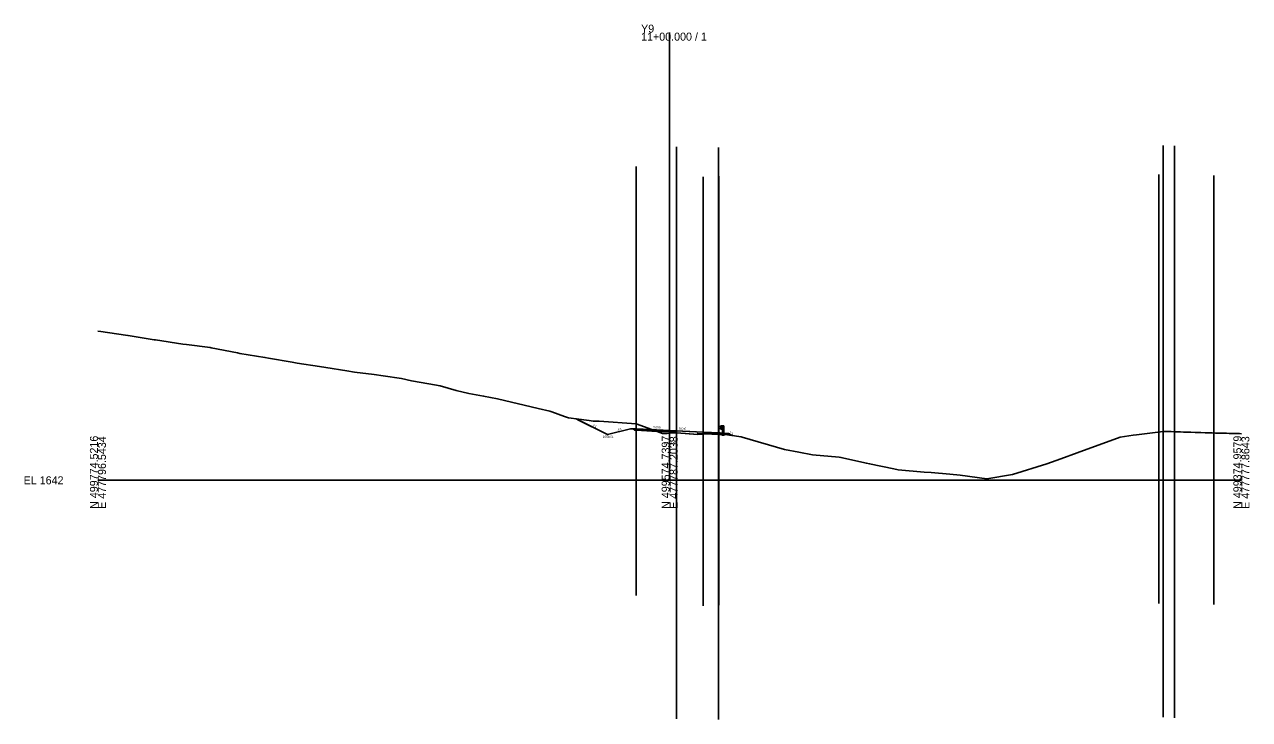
# Model space of a CAD drawing. Extents: x -26 to 403, y -99 to 4540.
# Drawn here: x -25.7 to 402.8, y 916.4 to 1159.4 of the extents above; entities that cross this region are included whole.
import ezdxf

# ---------------------------------------------------------------- set-up
doc = ezdxf.new("R2010")
doc.units = 0
for name, color, linetype in [('Exist Cross Section Cell', 7, 'Continuous'), ('Exist XS Center Line Elevation Label', 7, 'Continuous'), ('Exist XS Ground Line', 7, 'Continuous'), ('Prop XS Ditch Slope Text', 7, 'Continuous'), ('Prop XS Ditch Standard Text', 7, 'Continuous'), ('Prop XS Dump Level', 7, 'Continuous'), ('Prop XS Earthwork Shape', 7, 'Continuous'), ('Prop XS EOT Tick Mark', 7, 'Continuous'), ('Prop XS Finish Grade', 7, 'Continuous'), ('Prop XS Finish Grade Earthwork', 7, 'Continuous'), ('Prop XS Finish Grade Paved Shoulder', 7, 'Continuous'), ('Prop XS Finish Grade Pavement', 7, 'Continuous'), ('Prop XS Guardrail', 7, 'Continuous'), ('Prop XS Hydro Typical Ditch Data', 7, 'Continuous'), ('Prop XS Pvmt Edge Slope', 7, 'Continuous'), ('Prop XS SE Text', 7, 'Continuous'), ('Prop XS Shoulder Borrow Shape', 7, 'Continuous'), ('Prop XS Side Slope Text', 7, 'Continuous'), ('Prop XS Subgrade Earthwork', 7, 'Continuous'), ('Scratch_Level_1', 7, 'Continuous'), ('Scratch_Level_2', 7, 'Continuous'), ('Scratch_Level_5', 7, 'Continuous'), ('Scratch_Level_6', 7, 'Continuous')]:
    doc.layers.add(name, color=color, linetype=linetype)

msp = doc.modelspace()

# ---------------------------------------------------------------- linework, layer by layer
at = {"layer": 'Exist Cross Section Cell'}
for p, q in [((200, 1000), (200, 1156.54)), ((0, 1000), (200, 1000)), ((200, 1000), (400, 1000))]:
    msp.add_line(p, q, dxfattribs=at)
at = {"layer": 'Exist XS Ground Line'}
msp.add_lwpolyline([(0, 1052.18), (0.99, 1052.04), (9.6, 1050.76), (10.56, 1050.58), (19.62, 1049.15), (20.13, 1049.09), (29.69, 1047.62), (31.03, 1047.45), (39.26, 1046.4), (39.64, 1046.34), (48.82, 1044.55), (49.65, 1044.39), (58.39, 1042.98), (59.67, 1042.73), (67.95, 1041.28), (69.68, 1041), (77.52, 1039.74), (79.69, 1039.41), (87.09, 1038.28), (89.71, 1037.84), (96.65, 1036.96), (99.72, 1036.52), (106.22, 1035.55), (109.73, 1034.84), (115.78, 1033.71), (119.74, 1033.01), (125.35, 1031.36), (129.76, 1030.39), (134.91, 1029.48), (139.77, 1028.52), (153.97, 1025.14), (158.05, 1024.18), (158.79, 1023.92), (163.22, 1022.34), (164.56, 1021.87), (171.85, 1020.9), (173.26, 1020.73), (175.35, 1020.64), (188.27, 1019.77), (193.75, 1017.82), (197.47, 1016.41), (199.18, 1016.39), (200, 1016.45), (202.39, 1016.62), (205.54, 1016.38), (209.83, 1016.02), (213.44, 1016.28), (217.04, 1016.36), (224.98, 1015.23), (225.42, 1015.1), (240.14, 1010.83), (245.22, 1009.83), (249.91, 1008.92), (259.27, 1008.1), (259.92, 1008), (268.83, 1005.96), (269.94, 1005.77), (278.4, 1004.04), (279.96, 1003.71), (289, 1002.81), (291.43, 1002.7), (297.96, 1002.18), (301.61, 1001.76), (310.96, 1000.52), (319.97, 1002.04), (331.92, 1005.71), (336.79, 1007.52), (342.54, 1009.56), (357.6, 1015.14), (362.12, 1015.8), (363.27, 1015.94), (365.16, 1016.18), (368.88, 1016.64), (372.6, 1017.12), (374.23, 1017.05), (374.6, 1017.03), (375.39, 1017.01), (376.59, 1016.97), (377.89, 1016.92), (378.66, 1016.9), (379.78, 1016.86), (380.58, 1016.84), (382.3, 1016.78), (383.84, 1016.74), (384.78, 1016.71), (385.82, 1016.68), (387.29, 1016.64), (388.63, 1016.61), (389.79, 1016.57), (391, 1016.54), (392.3, 1016.5), (393.74, 1016.47), (394.81, 1016.44), (395.78, 1016.41), (397.29, 1016.37), (398.49, 1016.34), (399.37, 1016.32), (400, 1016.31)], dxfattribs=at)
at = {"layer": 'Prop XS Dump Level'}
for p, q in [((191, 1017.89), (200, 1017.44)), ((200, 1017.44), (209, 1016.99))]:
    msp.add_line(p, q, dxfattribs=at)
at = {"layer": 'Prop XS Earthwork Shape'}
for points in [[(187.28, 1018.02), (186.3, 1018.01), (178.3, 1016.01), (167.3, 1021.5), (171.85, 1020.9), (173.26, 1020.73), (175.35, 1020.64), (188.27, 1019.77), (193.75, 1017.82), (195.6, 1017.12), (188.3, 1017.48), (187.78, 1017.51)], [(200, 1016.45), (202.39, 1016.62), (202.39, 1016.78), (200, 1016.9), (195.6, 1017.12), (197.47, 1016.41), (199.18, 1016.39)], [(211.7, 1016.31), (209.83, 1016.41), (209.83, 1016.02), (212.98, 1016.25)], [(217.04, 1016.36), (217.96, 1016.23), (217.74, 1016.01), (217.17, 1016.04), (212.98, 1016.25), (213.44, 1016.28)], [(219.17, 1016.42), (221.1, 1015.78), (217.96, 1016.23), (218.23, 1016.5)]]:
    msp.add_lwpolyline(points, close=True, dxfattribs=at)
at = {"layer": 'Prop XS EOT Tick Mark'}
for p, q in [((188.3, 1018.03), (188.3, 1019.03)), ((211.7, 1016.86), (211.7, 1017.86))]:
    msp.add_line(p, q, dxfattribs=at)
at = {"layer": 'Prop XS Finish Grade'}
for p, q in [((188.3, 1018.03), (187.28, 1018.02)), ((217.61, 1016.56), (218.66, 1016.48))]:
    msp.add_line(p, q, dxfattribs=at)
at = {"layer": 'Prop XS Finish Grade Earthwork'}
for p, q in [((178.3, 1016.01), (167.3, 1021.5)), ((186.3, 1018.01), (178.3, 1016.01)), ((187.28, 1018.02), (186.3, 1018.01)), ((218.66, 1016.48), (220.61, 1016.32)), ((220.6, 1016.32), (221.91, 1015.67))]:
    msp.add_line(p, q, dxfattribs=at)
at = {"layer": 'Prop XS Finish Grade Paved Shoulder'}
msp.add_line((211.7, 1016.86), (217.61, 1016.56), dxfattribs=at)
at = {"layer": 'Prop XS Finish Grade Pavement'}
for p, q in [((188.3, 1018.03), (200, 1017.44)), ((200, 1017.44), (211.7, 1016.86))]:
    msp.add_line(p, q, dxfattribs=at)
at = {"layer": 'Prop XS Guardrail'}
for p, q in [((217.93, 1019.04), (217.64, 1018.84)), ((217.93, 1018.51), (217.64, 1018.71)), ((217.93, 1018.41), (217.64, 1018.21)), ((217.93, 1017.88), (217.64, 1018.08)), ((218.43, 1019.04), (217.93, 1019.04)), ((217.93, 1019.04), (217.93, 1017.88)), ((217.93, 1018.46), (217.93, 1018.51)), ((217.93, 1018.46), (217.93, 1018.41)), ((218.43, 1017.88), (217.93, 1017.88)), ((218.43, 1019.04), (218.43, 1016.55)), ((218.43, 1019.04), (218.92, 1019.04)), ((218.43, 1016.55), (218.92, 1016.55)), ((218.43, 1016.55), (218.43, 1015.54)), ((218.92, 1019.04), (218.92, 1016.55)), ((218.92, 1016.55), (218.92, 1015.54))]:
    msp.add_line(p, q, dxfattribs=at)
for centre, start, end in [((217.68, 1018.77), 125.003, 235.0112), ((217.68, 1018.15), 125.0059, 235.0366)]:
    msp.add_arc(centre, 0.0776, start, end, dxfattribs=at)
at = {"layer": 'Prop XS Hydro Typical Ditch Data'}
for p, q in [((178.3, 1016.01), (167.91, 1021.2)), ((186.3, 1018.01), (178.3, 1016.01))]:
    msp.add_line(p, q, dxfattribs=at)
at = {"layer": 'Prop XS Pvmt Edge Slope'}
for p, q in [((188.3, 1018.03), (187.78, 1017.51)), ((217.61, 1016.56), (218.18, 1015.99))]:
    msp.add_line(p, q, dxfattribs=at)
at = {"layer": 'Prop XS Shoulder Borrow Shape'}
for points in [[(188.3, 1018.03), (187.28, 1018.02), (187.78, 1017.51)], [(217.17, 1016.58), (218.23, 1016.5), (217.74, 1016.01)]]:
    msp.add_lwpolyline(points, close=True, dxfattribs=at)
at = {"layer": 'Prop XS Subgrade Earthwork'}
for p, q in [((187.78, 1017.51), (187.28, 1018.02)), ((188.3, 1017.48), (187.78, 1017.51)), ((200, 1016.9), (188.3, 1017.48)), ((202.39, 1016.78), (200, 1016.9)), ((202.39, 1016.62), (202.39, 1016.78)), ((211.7, 1016.31), (209.83, 1016.41)), ((209.83, 1016.02), (209.83, 1016.41)), ((211.69, 1016.31), (217.61, 1016.02)), ((217.61, 1016.02), (218.18, 1015.99)), ((218.18, 1015.99), (218.66, 1016.48))]:
    msp.add_line(p, q, dxfattribs=at)
at = {"layer": 'Scratch_Level_1'}
for p, q in [((202.39, 1116.62), (202.39, 916.62)), ((217.04, 1116.36), (217.04, 916.36)), ((372.6, 1117.12), (372.6, 917.12)), ((376.59, 1116.97), (376.59, 916.97))]:
    msp.add_line(p, q, dxfattribs=at)
at = {"layer": 'Scratch_Level_2'}
for p, q in [((217.17, 1066.34), (217.17, 966.34)), ((371.12, 1066.93), (371.12, 966.93))]:
    msp.add_line(p, q, dxfattribs=at)
at = {"layer": 'Scratch_Level_5'}
for p, q in [((217.17, 1106.34), (217.17, 956.34)), ((371.12, 1106.93), (371.12, 956.93))]:
    msp.add_line(p, q, dxfattribs=at)
at = {"layer": 'Scratch_Level_6'}
for p, q in [((188.3, 1109.76), (188.3, 959.76)), ((211.7, 1106.16), (211.7, 956.16)), ((217.17, 1106.34), (217.17, 956.34)), ((371.12, 1106.93), (371.12, 956.93)), ((390.35, 1106.56), (390.35, 956.56)), ((202.39, 1016.62), (209.83, 1016.02))]:
    msp.add_line(p, q, dxfattribs=at)

# ---------------------------------------------------------------- texts
at = {"layer": 'Exist Cross Section Cell'}
for s, p in [('Y9', (190, 1156.54)), ('11+00.000 / 1', (190, 1153.74)), ('EL 1642', (-26, 998.6))]:
    msp.add_text(s, height=2.8, dxfattribs=at).set_placement(p)
for s, p in [('N 499774.5216', (0, 990)), ('E 477796.5434', (2.8, 990)), ('N 499574.7397', (200, 990)), ('E 477787.2038', (202.8, 990)), ('N 499374.9579', (400, 990)), ('E 477777.8643', (402.8, 990))]:
    msp.add_text(s, height=2.8, rotation=90, dxfattribs=at).set_placement(p)
at = {"layer": 'Exist XS Center Line Elevation Label'}
msp.add_text('1658.45', height=0.9, dxfattribs=at).set_placement((197.88, 1012.55))
at = {"layer": 'Prop XS Ditch Slope Text'}
for s, rotation, p in [('4:1', 14.0362, (181.89, 1017.32)), ('2:1', 339.1603, (220.82, 1016.37))]:
    msp.add_text(s, height=0.75, rotation=rotation, dxfattribs=at).set_placement(p)
at = {"layer": 'Prop XS Ditch Standard Text'}
msp.add_text('1658.01', height=0.75, dxfattribs=at).set_placement((176.65, 1014.85))
at = {"layer": 'Prop XS Dump Level'}
for p in [(186.3, 1017.97), (220.6, 1016.28)]:
    msp.add_text('Case1', height=0.04, dxfattribs=at).set_placement(p)
at = {"layer": 'Prop XS SE Text'}
for p in [(194.19, 1018.23), (203.19, 1017.78)]:
    msp.add_text('0.050', height=0.75, rotation=357.1376, dxfattribs=at).set_placement(p)
at = {"layer": 'Prop XS Side Slope Text'}
msp.add_text('2:1', height=0.75, rotation=333.4349, dxfattribs=at).set_placement((172.95, 1019.03))

doc.saveas('drawing.dxf')
